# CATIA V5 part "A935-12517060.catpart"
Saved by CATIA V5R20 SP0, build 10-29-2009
Part number: A935-12517060
Source: Unknown
Property "A": "85.000"
Property "ARTICLENO": "A935-12517060"
Property "B": "30.000"
Property "BOMINFO": "A935-12517060"
Property "CODE": "A935-12517060"
Property "L": "170.000"
Property "L1": "127.860"
Property "LINA": "A935-12517060"
Property "NB": "A935-12517060"
Property "NBSYN": "$CODE."
Property "NN": "A935"
Property "NT": "VDI 3357 H-Type Cam Drivers, steel (16MnCr5)"
Property "SUPPLIER": "CF"
Property "T": "60.000"
Property "W": "125.000"
Bounding box of the stored display mesh (mm): x 0 to 170, y 0 to 60, z -125 to 0
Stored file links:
  C:\Users\Utente\Desktop\3D files A935\A935-12517060.catpart
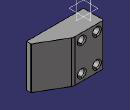
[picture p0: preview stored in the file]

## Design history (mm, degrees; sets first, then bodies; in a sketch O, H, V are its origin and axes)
Body1 "Geometry.1" (main body)
  Solid1 "A935-12517060.catpart": solid without history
